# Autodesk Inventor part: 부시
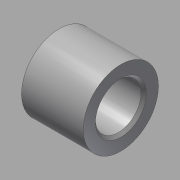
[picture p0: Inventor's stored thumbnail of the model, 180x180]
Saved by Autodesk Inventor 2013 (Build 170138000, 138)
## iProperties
Created: 2016-10
Part Number: 부시
Material: 강철, 연강
Document SubType Name: Modeling
Designer: mduedu
Density: 1 g/cm^3
Author: mduedu
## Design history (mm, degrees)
sketch "스케치1"
  geometry: C1 r 14 at (0, 0); C2 r 8.5 at (0, 0); 1 further point
  constraints: 2 centre point, 2 coincident
  dimensions: "d0" = 28 diameter of C1; "d1" = 17 diameter of C2
extrude "돌출1" new body sketch "스케치1" distance "d2" = 23; taper "d3" = 0 deg
chamfer "모따기1" distance "d4" = 1; stored, may be unused: second distance "d5" = 2, angle "d6" = 45 deg
node "솔리드1"
